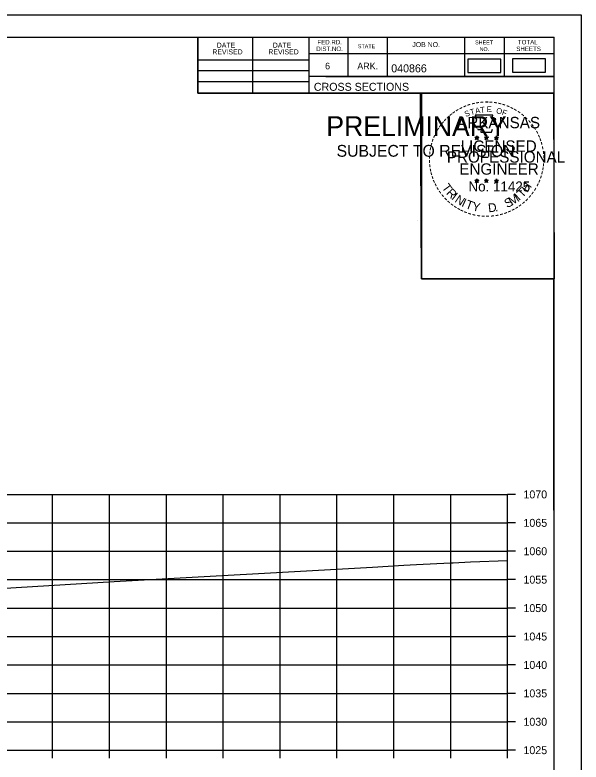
# Model space of a CAD drawing. Extents: x 1370565 to 1374448, y 301010 to 304637.
# Drawn here: x 1370798.4 to 1370898, y 303865.8 to 303997.2 of the extents above; entities that cross this region are included whole.
import ezdxf

# ---------------------------------------------------------------- set-up
doc = ezdxf.new("R2010")
doc.units = 0
for name, color, linetype in [('Default', 7, 'Continuous'), ('R_Axis', 7, 'Continuous'), ('R_Axis Annot', 7, 'Continuous'), ('R_Border', 7, 'Continuous'), ('R_Border PE', 7, 'Continuous'), ('R_Border Prem', 7, 'Continuous'), ('R_Drive', 7, 'Continuous'), ('R_Exist Surface', 7, 'Continuous'), ('R_Grid', 7, 'Continuous'), ('R_No Plot', 7, 'Continuous')]:
    doc.layers.add(name, color=color, linetype=linetype)

msp = doc.modelspace()

# ---------------------------------------------------------------- linework, layer by layer
at = {"layer": 'Default'}
msp.add_lwpolyline([(1370878.02, 303987.11), (1370883.85, 303987.11), (1370883.85, 303989.42), (1370878.02, 303989.42)], close=True, dxfattribs=at)
at = {"layer": 'R_Axis'}
for p, q in [((1370885.03, 303867.87), (1370885.03, 303912.87)), ((1370886.43, 303912.87), (1370885.03, 303912.87)), ((1370886.43, 303907.87), (1370885.03, 303907.87)), ((1370886.43, 303902.87), (1370885.03, 303902.87)), ((1370886.43, 303897.87), (1370885.03, 303897.87)), ((1370886.43, 303892.87), (1370885.03, 303892.87)), ((1370886.43, 303887.87), (1370885.03, 303887.87)), ((1370886.43, 303882.87), (1370885.03, 303882.87)), ((1370886.43, 303877.87), (1370885.03, 303877.87)), ((1370886.43, 303872.87), (1370885.03, 303872.87)), ((1370585.03, 303867.87), (1370885.03, 303867.87)), ((1370805.03, 303866.47), (1370805.03, 303867.87)), ((1370815.03, 303866.47), (1370815.03, 303867.87)), ((1370825.03, 303866.47), (1370825.03, 303867.87)), ((1370835.03, 303866.47), (1370835.03, 303867.87)), ((1370845.03, 303866.47), (1370845.03, 303867.87)), ((1370855.03, 303866.47), (1370855.03, 303867.87)), ((1370865.03, 303866.47), (1370865.03, 303867.87)), ((1370875.03, 303866.47), (1370875.03, 303867.87)), ((1370885.03, 303866.47), (1370885.03, 303867.87)), ((1370886.43, 303867.87), (1370885.03, 303867.87))]:
    msp.add_line(p, q, dxfattribs=at)
at = {"layer": 'R_Border'}
for p, q in [((1370577.03, 303993.33), (1370893.21, 303993.33)), ((1370830.57, 303983.45), (1370830.57, 303993.33)), ((1370840.25, 303983.45), (1370840.25, 303993.33)), ((1370850.11, 303993.33), (1370850.11, 303983.45)), ((1370856.95, 303993.33), (1370856.95, 303986.39)), ((1370863.89, 303993.33), (1370863.89, 303986.39)), ((1370877.47, 303993.33), (1370877.47, 303986.39)), ((1370884.41, 303993.33), (1370884.41, 303986.39)), ((1370893.21, 303787.87), (1370893.21, 303993.33)), ((1370893.21, 303990.39), (1370850.11, 303990.39)), ((1370893.21, 303990.41), (1370893.21, 303990.41)), ((1370830.57, 303989.31), (1370850.11, 303989.31)), ((1370830.57, 303987.45), (1370850.11, 303987.45)), ((1370893.21, 303986.39), (1370850.11, 303986.39)), ((1370853.07, 303986.39), (1370893.21, 303986.39)), ((1370830.57, 303985.51), (1370850.11, 303985.51)), ((1370893.21, 303983.45), (1370830.57, 303983.45))]:
    msp.add_line(p, q, dxfattribs=at)
at = {"layer": 'R_Border PE'}
for p, q in [((1370879.29, 303975.7), (1370879.64, 303975.59)), ((1370879.29, 303975.7), (1370879.54, 303975.66)), ((1370879.29, 303975.7), (1370879.53, 303975.58)), ((1370879.42, 303975.3), (1370879.64, 303975.59)), ((1370879.42, 303975.3), (1370879.55, 303975.54)), ((1370879.42, 303975.3), (1370879.64, 303975.51)), ((1370879.64, 303975.96), (1370879.6, 303975.71)), ((1370879.64, 303975.59), (1370879.64, 303975.96)), ((1370879.64, 303975.96), (1370879.69, 303975.71)), ((1370879.99, 303975.7), (1370879.64, 303975.59)), ((1370879.85, 303975.3), (1370879.64, 303975.59)), ((1370879.85, 303975.3), (1370879.64, 303975.51)), ((1370879.99, 303975.7), (1370879.7, 303975.66)), ((1370879.85, 303975.3), (1370879.72, 303975.59)), ((1370879.99, 303975.7), (1370879.78, 303975.6)), ((1370880.96, 303975.7), (1370881.31, 303975.59)), ((1370880.96, 303975.7), (1370881.21, 303975.66)), ((1370880.96, 303975.7), (1370881.2, 303975.58)), ((1370881.09, 303975.3), (1370881.31, 303975.59)), ((1370881.09, 303975.3), (1370881.22, 303975.54)), ((1370881.09, 303975.3), (1370881.31, 303975.51)), ((1370881.31, 303975.96), (1370881.27, 303975.71)), ((1370881.31, 303975.59), (1370881.31, 303975.96)), ((1370881.31, 303975.96), (1370881.36, 303975.71)), ((1370881.66, 303975.7), (1370881.31, 303975.59)), ((1370881.52, 303975.3), (1370881.31, 303975.59)), ((1370881.52, 303975.3), (1370881.31, 303975.51)), ((1370881.66, 303975.7), (1370881.37, 303975.66)), ((1370881.52, 303975.3), (1370881.39, 303975.59)), ((1370881.66, 303975.7), (1370881.45, 303975.6)), ((1370882.72, 303975.69), (1370883.07, 303975.58)), ((1370882.72, 303975.69), (1370882.98, 303975.65)), ((1370882.72, 303975.69), (1370882.96, 303975.57)), ((1370882.86, 303975.28), (1370883.07, 303975.58)), ((1370882.86, 303975.28), (1370882.98, 303975.53)), ((1370882.86, 303975.28), (1370883.07, 303975.5)), ((1370883.07, 303975.95), (1370883.03, 303975.69)), ((1370883.07, 303975.58), (1370883.07, 303975.95)), ((1370883.07, 303975.95), (1370883.12, 303975.7)), ((1370883.42, 303975.69), (1370883.07, 303975.58)), ((1370883.29, 303975.28), (1370883.07, 303975.58)), ((1370883.29, 303975.28), (1370883.07, 303975.5)), ((1370883.42, 303975.69), (1370883.13, 303975.64)), ((1370883.29, 303975.28), (1370883.15, 303975.58)), ((1370883.42, 303975.69), (1370883.22, 303975.59)), ((1370879.29, 303968.13), (1370879.64, 303968.02)), ((1370879.29, 303968.13), (1370879.54, 303968.09)), ((1370879.29, 303968.13), (1370879.52, 303968.01)), ((1370879.42, 303967.72), (1370879.64, 303968.02)), ((1370879.42, 303967.72), (1370879.55, 303967.97)), ((1370879.42, 303967.72), (1370879.63, 303967.94)), ((1370879.64, 303968.39), (1370879.59, 303968.13)), ((1370879.85, 303967.72), (1370879.63, 303967.94)), ((1370879.64, 303968.02), (1370879.64, 303968.39)), ((1370879.64, 303968.39), (1370879.68, 303968.14)), ((1370879.98, 303968.13), (1370879.64, 303968.02)), ((1370879.85, 303967.72), (1370879.64, 303968.02)), ((1370879.98, 303968.13), (1370879.7, 303968.08)), ((1370879.85, 303967.72), (1370879.71, 303968.01)), ((1370879.98, 303968.13), (1370879.78, 303968.03)), ((1370880.96, 303968.13), (1370881.3, 303968.02)), ((1370880.96, 303968.13), (1370881.21, 303968.09)), ((1370880.96, 303968.13), (1370881.19, 303968.01)), ((1370881.09, 303967.72), (1370881.3, 303968.02)), ((1370881.09, 303967.72), (1370881.21, 303967.97)), ((1370881.09, 303967.72), (1370881.3, 303967.94)), ((1370881.3, 303968.39), (1370881.26, 303968.13)), ((1370881.3, 303968.02), (1370881.3, 303968.39)), ((1370881.3, 303968.39), (1370881.35, 303968.14)), ((1370881.65, 303968.13), (1370881.3, 303968.02)), ((1370881.52, 303967.72), (1370881.3, 303968.02)), ((1370881.52, 303967.72), (1370881.3, 303967.94)), ((1370881.65, 303968.13), (1370881.37, 303968.08)), ((1370881.52, 303967.72), (1370881.38, 303968.01)), ((1370881.65, 303968.13), (1370881.45, 303968.03)), ((1370882.72, 303968.12), (1370883.07, 303968.01)), ((1370882.72, 303968.12), (1370882.98, 303968.08)), ((1370882.72, 303968.12), (1370882.96, 303968)), ((1370882.86, 303967.71), (1370883.07, 303968.01)), ((1370882.86, 303967.71), (1370882.98, 303967.96)), ((1370882.86, 303967.71), (1370883.07, 303967.93)), ((1370883.07, 303968.38), (1370883.03, 303968.12)), ((1370883.07, 303968.01), (1370883.07, 303968.38)), ((1370883.07, 303968.38), (1370883.12, 303968.13)), ((1370883.42, 303968.12), (1370883.07, 303968.01)), ((1370883.28, 303967.71), (1370883.07, 303968.01)), ((1370883.28, 303967.71), (1370883.07, 303967.93)), ((1370883.42, 303968.12), (1370883.13, 303968.07)), ((1370883.28, 303967.71), (1370883.15, 303968)), ((1370883.42, 303968.12), (1370883.21, 303968.02))]:
    msp.add_line(p, q, dxfattribs=at)
for points in [[(1370879.33, 303979.58), (1370879.6, 303978.76)], [(1370882.84, 303978.66), (1370882.98, 303978.94), (1370882.3, 303978.92), (1370882.45, 303979.58), (1370879.33, 303979.58)], [(1370879.82, 303977.16), (1370879.82, 303977.07), (1370880.39, 303977.05), (1370880.33, 303976.58), (1370882.2, 303976.58), (1370882.4, 303977.12)], [(1370879.64, 303975.96), (1370879.85, 303975.3), (1370879.29, 303975.7), (1370879.99, 303975.7), (1370879.42, 303975.3), (1370879.64, 303975.96)], [(1370881.31, 303975.96), (1370881.52, 303975.3), (1370880.96, 303975.7), (1370881.66, 303975.7), (1370881.09, 303975.3), (1370881.31, 303975.96)], [(1370883.07, 303975.95), (1370883.29, 303975.28), (1370882.72, 303975.69), (1370883.42, 303975.69), (1370882.86, 303975.28), (1370883.07, 303975.95)], [(1370879.64, 303968.39), (1370879.85, 303967.72), (1370879.29, 303968.13), (1370879.98, 303968.13), (1370879.42, 303967.72), (1370879.64, 303968.39)], [(1370881.3, 303968.39), (1370881.52, 303967.72), (1370880.96, 303968.13), (1370881.65, 303968.13), (1370881.09, 303967.72), (1370881.3, 303968.39)], [(1370883.07, 303968.38), (1370883.28, 303967.71), (1370882.72, 303968.12), (1370883.42, 303968.12), (1370882.86, 303967.71), (1370883.07, 303968.38)]]:
    msp.add_lwpolyline(points, dxfattribs=at)
for centre, radius in [((1370879.64, 303975.59), 0.172), ((1370879.64, 303975.59), 0.145), ((1370879.64, 303975.59), 0.116), ((1370879.64, 303975.59), 0.0991), ((1370879.64, 303975.59), 0.0747), ((1370879.64, 303975.59), 0.0495), ((1370879.64, 303975.59), 0.0296), ((1370881.31, 303975.59), 0.172), ((1370881.31, 303975.59), 0.145), ((1370881.31, 303975.59), 0.116), ((1370881.31, 303975.59), 0.0991), ((1370881.31, 303975.59), 0.0747), ((1370881.31, 303975.59), 0.0495), ((1370881.31, 303975.59), 0.0296), ((1370883.07, 303975.58), 0.172), ((1370883.07, 303975.58), 0.145), ((1370883.07, 303975.58), 0.116), ((1370883.07, 303975.58), 0.0991), ((1370883.07, 303975.58), 0.0747), ((1370883.07, 303975.58), 0.0495), ((1370883.07, 303975.58), 0.0296), ((1370879.63, 303968.02), 0.172), ((1370879.63, 303968.02), 0.145), ((1370879.63, 303968.02), 0.116), ((1370879.63, 303968.02), 0.0991), ((1370879.63, 303968.02), 0.0747), ((1370879.63, 303968.02), 0.0495), ((1370879.63, 303968.02), 0.0296), ((1370881.3, 303968.02), 0.172), ((1370881.3, 303968.02), 0.145), ((1370881.3, 303968.02), 0.116), ((1370881.3, 303968.02), 0.0991), ((1370881.3, 303968.02), 0.0747), ((1370881.3, 303968.02), 0.0495), ((1370881.3, 303968.02), 0.0296), ((1370883.07, 303968.01), 0.172), ((1370883.07, 303968.01), 0.145), ((1370883.07, 303968.01), 0.116), ((1370883.07, 303968.01), 0.0991), ((1370883.07, 303968.01), 0.0747), ((1370883.07, 303968.01), 0.0495), ((1370883.07, 303968.01), 0.0296)]:
    msp.add_circle(centre, radius, dxfattribs=at)
at = {"layer": 'R_Drive'}
msp.add_lwpolyline([(1370885.89, 303987.18), (1370891.72, 303987.18), (1370891.72, 303989.49), (1370885.89, 303989.49)], close=True, dxfattribs=at)
at = {"layer": 'R_Exist Surface'}
msp.add_lwpolyline([(1370696, 303888.59), (1370703.85, 303888.5), (1370711.23, 303889.7), (1370725.04, 303891.95), (1370731.74, 303892.07), (1370734.74, 303892.13), (1370741.99, 303892.07), (1370744.91, 303892.04), (1370755.32, 303890.95), (1370759.31, 303890.51), (1370765.77, 303892.21), (1370777.54, 303895.23), (1370815.85, 303897.56), (1370861.29, 303900.09), (1370866.81, 303900.4), (1370869.04, 303900.55), (1370875, 303900.84), (1370875.48, 303900.86), (1370878.51, 303900.98), (1370885.03, 303901.22)], dxfattribs=at)
at = {"layer": 'R_Grid'}
for p, q in [((1370585.03, 303912.87), (1370885.03, 303912.87)), ((1370805.03, 303867.87), (1370805.03, 303912.87)), ((1370815.03, 303867.87), (1370815.03, 303912.87)), ((1370825.03, 303867.87), (1370825.03, 303912.87)), ((1370835.03, 303867.87), (1370835.03, 303912.87)), ((1370845.03, 303867.87), (1370845.03, 303912.87)), ((1370855.03, 303867.87), (1370855.03, 303912.87)), ((1370865.03, 303867.87), (1370865.03, 303912.87)), ((1370875.03, 303867.87), (1370875.03, 303912.87)), ((1370885.03, 303867.87), (1370885.03, 303912.87)), ((1370585.03, 303907.87), (1370885.03, 303907.87)), ((1370585.03, 303902.87), (1370885.03, 303902.87)), ((1370585.03, 303897.87), (1370885.03, 303897.87)), ((1370585.03, 303892.87), (1370885.03, 303892.87)), ((1370585.03, 303887.87), (1370885.03, 303887.87)), ((1370585.03, 303882.87), (1370885.03, 303882.87)), ((1370585.03, 303877.87), (1370885.03, 303877.87)), ((1370585.03, 303872.87), (1370885.03, 303872.87)), ((1370585.03, 303867.87), (1370885.03, 303867.87))]:
    msp.add_line(p, q, dxfattribs=at)
at = {"layer": 'R_No Plot'}
for p, q in [((1370564.63, 303997.22), (1370897.96, 303997.22)), ((1370869.24, 303960.99), (1370869.24, 303960.99))]:
    msp.add_line(p, q, dxfattribs=at)
for points in [[(1370564.62, 303997.22), (1370897.96, 303997.22), (1370897.96, 303783.89), (1370564.62, 303783.89)], [(1370810.95, 303993.33), (1370830.57, 303993.33), (1370830.57, 303983.45), (1370846.68, 303983.45), (1370869.88, 303983.45), (1370869.88, 303950.78), (1370893.09, 303950.78), (1370893.21, 303787.87), (1370577.03, 303787.87), (1370577.03, 303993.33)], [(1370869.74, 303983.45), (1370893.09, 303983.45), (1370893.23, 303950.78), (1370869.88, 303950.78)]]:
    msp.add_lwpolyline(points, close=True, dxfattribs=at)

# ---------------------------------------------------------------- texts
at = {"layer": 'R_Axis Annot'}
for s, p in [('1070', (1370887.83, 303912.17)), ('1065', (1370887.83, 303907.17)), ('1060', (1370887.83, 303902.17)), ('1055', (1370887.83, 303897.17)), ('1050', (1370887.83, 303892.17)), ('1045', (1370887.83, 303887.17)), ('1040', (1370887.83, 303882.17)), ('1035', (1370887.83, 303877.17)), ('1030', (1370887.83, 303872.17)), ('1025', (1370887.83, 303867.17))]:
    msp.add_text(s, height=1.4, dxfattribs=at).set_placement(p)
at = {"layer": 'R_Border'}
for s, height, p in [('FED.RD.', 0.782, (1370851.59, 303992.05)), ('JOB NO.', 0.879, (1370868.29, 303991.57)), ('SHEET', 0.684, (1370879.33, 303992.05)), ('TOTAL', 0.782, (1370886.85, 303992.05)), ('REVISED', 0.879, (1370833.12, 303990.29)), ('DATE', 0.879, (1370833.9, 303991.47)), ('REVISED', 0.879, (1370842.98, 303990.29)), ('DATE', 0.879, (1370843.76, 303991.47)), ('DIST.NO.', 0.782, (1370851.39, 303990.87)), ('STATE', 0.684, (1370858.71, 303991.37)), ('NO.', 0.684, (1370880.11, 303990.87)), ('SHEETS', 0.782, (1370886.57, 303990.87)), ('6', 1.17, (1370852.95, 303987.65)), ('ARK.', 1.172, (1370858.61, 303987.65)), ('040866', 1.4, (1370864.58, 303987.13)), ('CROSS SECTIONS', 1.4, (1370850.97, 303983.88))]:
    msp.add_text(s, height=height, rotation=360, dxfattribs=at).set_placement(p)
at = {"layer": 'R_Border PE'}
for s, height, rotation, p in [('-', 1.6, 10.2193, (1370879.51, 303981.11)), ('-', 1.6, 5.8968, (1370880.24, 303981.22)), ('-', 1.6, 0.1862, (1370881.01, 303981.29)), ('-', 1.6, 357.743, (1370881.73, 303981.28)), ('-', 1.6, 352.1617, (1370882.48, 303981.23)), ('-', 1.6, 34.0636, (1370876.22, 303979.75)), ('-', 1.6, 28.7918, (1370876.81, 303980.12)), ('-', 1.6, 24.3072, (1370877.45, 303980.44)), ('-', 1.6, 19.1761, (1370878.08, 303980.71)), ('T', 1, 16.4036, (1370878.6, 303979.59)), ('-', 1.6, 13.6301, (1370878.83, 303980.95)), ('A', 1, 11.2132, (1370879.43, 303979.84)), ('T', 1, 6.0228, (1370880.28, 303980.01)), ('E', 1, 0.8323, (1370881.38, 303980.12)), ('O', 1, 350.4515, (1370882.98, 303979.91)), ('-', 1.6, 347.2049, (1370883.19, 303981.11)), ('F', 1, 340.0707, (1370883.94, 303979.68)), ('-', 1.6, 342.3362, (1370883.83, 303980.96)), ('-', 1.6, 337.8551, (1370884.56, 303980.73)), ('-', 1.6, 334.1211, (1370885.2, 303980.46)), ('-', 1.6, 329.6409, (1370885.77, 303980.18)), ('-', 1.6, 42.9622, (1370874.73, 303978.56)), ('-', 1.6, 38.9507, (1370875.16, 303978.98)), ('-', 1.6, 36.2317, (1370875.64, 303979.36)), ('ARKANSAS', 2, 360, (1370876.18, 303977.29)), ('S', 1, 21.594, (1370877.69, 303979.26)), ('-', 1.6, 325.8627, (1370886.42, 303979.82)), ('-', 1.6, 320.5297, (1370887.03, 303979.39)), ('-', 1.6, 315.5786, (1370887.63, 303978.9)), ('-', 1.6, 54.2325, (1370873.46, 303977.03)), ('-', 1.6, 50.6142, (1370873.88, 303977.6)), ('-', 1.6, 48.423, (1370874.28, 303978.09)), ('-', 1.6, 309.8797, (1370888.2, 303978.35)), ('-', 1.6, 306.6522, (1370888.72, 303977.75)), ('-', 1.6, 62.8713, (1370872.83, 303975.89)), ('-', 1.6, 58.0706, (1370873.14, 303976.51)), ('-', 1.4, 303.6753, (1370889.21, 303977.18)), ('-', 1.6, 299.6684, (1370889.53, 303976.58)), ('-', 1.6, 72.3945, (1370872.35, 303974.65)), ('-', 1.6, 67.7743, (1370872.57, 303975.28)), ('DWB', 0.01, 360, (1370879.63, 303975.59)), ('DWB', 0.01, 360, (1370881.3, 303975.59)), ('DWB', 0.01, 360, (1370883.06, 303975.58)), ('-', 1.6, 294.6628, (1370889.85, 303975.97)), ('-', 1.6, 290.5728, (1370890.11, 303975.39)), ('-', 1.6, 75.461, (1370872.15, 303973.94)), ('LICENSED', 2, 360, (1370876.78, 303973.15)), ('-', 1.6, 285.1233, (1370890.34, 303974.81)), ('-', 1.6, 280.5493, (1370890.54, 303974.07)), ('-', 1.6, 85.1863, (1370871.94, 303972.53)), ('-', 1.6, 81.2013, (1370872.02, 303973.22)), ('PROFESSIONAL', 2, 360, (1370874.36, 303971.24)), ('-', 1.6, 276.5962, (1370890.7, 303973.3)), ('-', 1.6, 94.1959, (1370871.95, 303971.11)), ('-', 1.6, 89.0622, (1370871.92, 303971.83)), ('-', 1.6, 274.3301, (1370890.76, 303972.58)), ('-', 1.6, 269.9407, (1370890.8, 303971.94)), ('-', 1.6, 98.9479, (1370872.03, 303970.44)), ('-', 1.6, 101.7149, (1370872.16, 303969.71)), ('ENGINEER', 2, 360, (1370876.55, 303969.12)), ('-', 1.6, 260.9953, (1370890.71, 303970.62)), ('-', 1.6, 263.5172, (1370890.78, 303971.28)), ('-', 1.6, 105.4578, (1370872.32, 303969.11)), ('-', 1.6, 109.0874, (1370872.54, 303968.48)), ('-', 1.6, 252.8681, (1370890.42, 303969.23)), ('-', 1.6, 255.7626, (1370890.6, 303969.95)), ('-', 1.6, 114.0643, (1370872.79, 303967.88)), ('-', 1.6, 115.7289, (1370873.1, 303967.27)), ('T', 1.54, 306.0406, (1370873.4, 303966.86)), ('No. 11425', 1.757, 360, (1370878.17, 303966.17)), ('DWB', 0.01, 360, (1370879.62, 303968.02)), ('DWB', 0.01, 360, (1370881.29, 303968.02)), ('DWB', 0.01, 360, (1370883.06, 303968.01)), ('H', 1.54, 54.6088, (1370888.52, 303965.89)), ('-', 1.6, 244.6197, (1370889.93, 303967.92)), ('-', 1.6, 247.8887, (1370890.19, 303968.55)), ('-', 1.6, 120.4471, (1370873.45, 303966.68)), ('-', 1.6, 125.8934, (1370873.86, 303966.12)), ('R', 1.54, 314.005, (1370874.16, 303965.81)), ('T', 1.54, 46.6444, (1370887.63, 303964.95)), ('-', 1.6, 233.8452, (1370889.13, 303966.52)), ('-', 1.6, 239.0712, (1370889.54, 303967.17)), ('-', 1.6, 130.7181, (1370874.32, 303965.57)), ('-', 1.6, 134.2238, (1370874.84, 303965.02)), ('I', 1.54, 321.9694, (1370875.06, 303964.88)), ('N', 1.54, 326.5002, (1370875.63, 303964.41)), ('I', 1.54, 335.3603, (1370876.83, 303963.62)), ('S', 1.54, 26.9312, (1370884.94, 303963.22)), ('M', 1.54, 32.6563, (1370885.78, 303963.63)), ('I', 1.54, 42.1136, (1370887.06, 303964.47)), ('-', 1.6, 225.7653, (1370888.23, 303965.39)), ('-', 1.6, 231.2538, (1370888.7, 303965.95)), ('-', 1.6, 138.9338, (1370875.36, 303964.56)), ('-', 1.6, 144.6463, (1370875.92, 303964.15)), ('-', 1.6, 148.0898, (1370876.48, 303963.78)), ('T', 1.54, 339.8912, (1370877.49, 303963.29)), ('Y', 1.54, 347.8556, (1370878.71, 303962.85)), ('D', 1.54, 6.3969, (1370881.7, 303962.49)), ('-', 1.6, 212.2491, (1370886.62, 303964.02)), ('-', 1.6, 215.7363, (1370887.15, 303964.41)), ('-', 1.6, 221.0851, (1370887.7, 303964.88)), ('-', 1.6, 151.5704, (1370877.06, 303963.46)), ('-', 1.6, 154.6002, (1370877.58, 303963.21)), ('-', 1.6, 158.5612, (1370878.2, 303962.96)), ('-', 1.6, 162.7983, (1370878.89, 303962.74)), ('-', 1.6, 167.5555, (1370879.6, 303962.58)), ('.', 1.54, 13.7642, (1370882.89, 303962.62)), ('-', 1.6, 195.4743, (1370884.14, 303962.84)), ('-', 1.6, 200.7184, (1370884.82, 303963.08)), ('-', 1.6, 204.2516, (1370885.44, 303963.36)), ('-', 1.6, 207.3568, (1370886.06, 303963.68)), ('-', 1.6, 173.1155, (1370880.38, 303962.47)), ('-', 1.6, 176.5183, (1370881.12, 303962.42)), ('-', 1.6, 181.5918, (1370881.87, 303962.43)), ('-', 1.6, 185.8167, (1370882.68, 303962.51)), ('-', 1.6, 191.2858, (1370883.41, 303962.64))]:
    msp.add_text(s, height=height, rotation=rotation, dxfattribs=at).set_placement(p)
at = {"layer": 'R_Border Prem'}
for s, height, p in [('PRELIMINARY', 3.5, (1370853.16, 303975.91)), ('DWB', 0.01, (1370853.9, 303977.76)), ('SUBJECT TO REVISION', 2.0751, (1370854.97, 303972.28))]:
    msp.add_text(s, height=height, rotation=360, dxfattribs=at).set_placement(p)

doc.saveas('drawing.dxf')
